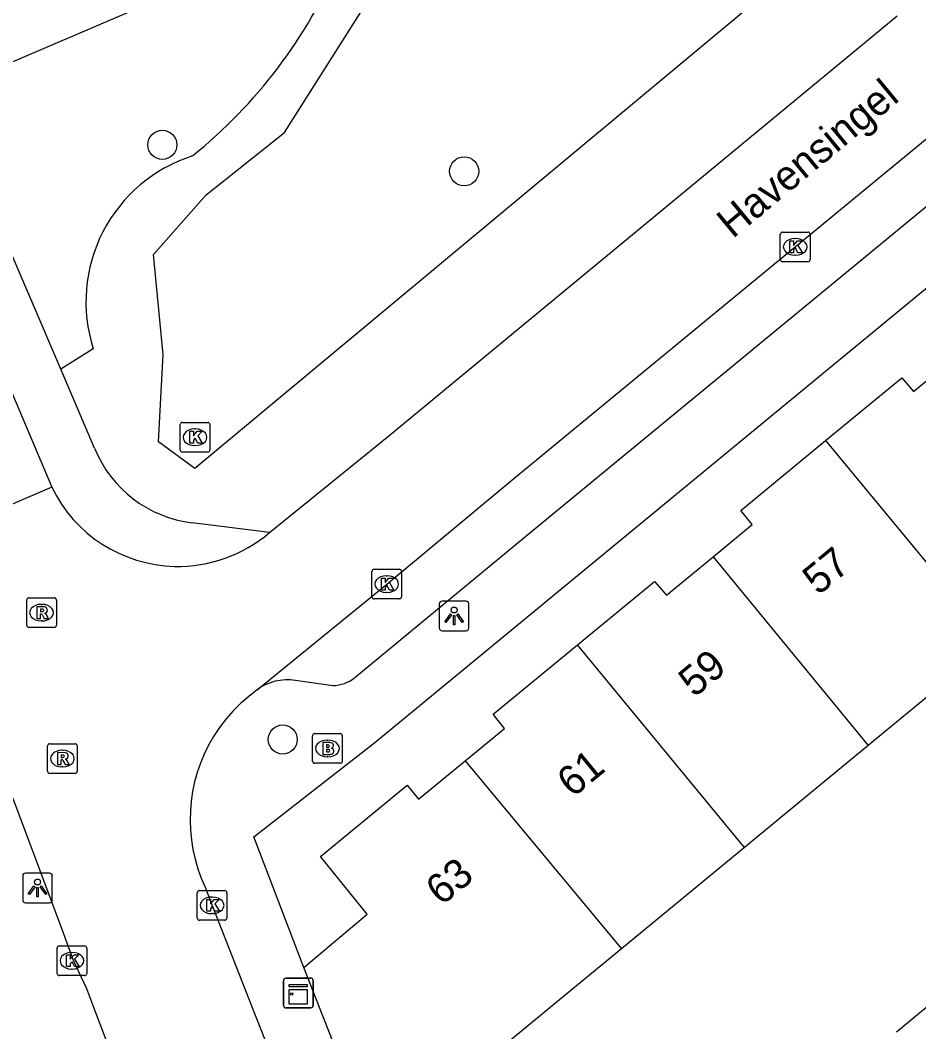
# Model space of a CAD drawing. Extents: x 161771 to 163125, y 382479 to 383177.
# Drawn here: x 161946.47 to 161976.75, y 382999.19 to 383033.26 of the extents above; entities that cross this region are included whole.
import ezdxf

# ---------------------------------------------------------------- set-up
doc = ezdxf.new("R2010")
doc.units = 0
for name, color, linetype in [('IMGEO_Boom', 7, 'Continuous'), ('IMGEO_Brandkraan', 7, 'Continuous'), ('IMGEO_Groenvoorziening', 7, 'Continuous'), ('IMGEO_Kast', 7, 'Continuous'), ('IMGEO_Kolk', 7, 'Continuous'), ('IMGEO_Lichtpunt', 7, 'Continuous'), ('IMGEO_Openbare_ruimte_label', 7, 'Continuous'), ('IMGEO_Pand', 7, 'Continuous'), ('IMGEO_Pand_nummerreeks', 7, 'Continuous'), ('IMGEO_Rijbaan_lokaal_open', 7, 'Continuous'), ('IMGEO_Rioolput', 7, 'Continuous'), ('IMGEO_Voetpad_open', 7, 'Continuous')]:
    doc.layers.add(name, color=color, linetype=linetype)

msp = doc.modelspace()

# ---------------------------------------------------------------- linework, layer by layer
at = {"layer": 'IMGEO_Boom'}
for centre in [(161951.257, 383029.066), (161961.429, 383028.173), (161955.314, 383009.031)]:
    msp.add_circle(centre, 0.489, dxfattribs=at)
at = {"layer": 'IMGEO_Brandkraan'}
for p, q in [((161956.397, 383009.229), (161957.249, 383009.229)), ((161956.322, 383008.303), (161956.322, 383009.155)), ((161956.81, 383009.009), (161956.835, 383009.009)), ((161957.323, 383009.155), (161957.323, 383008.303)), ((161957.249, 383008.229), (161956.397, 383008.229)), ((161956.833, 383008.449), (161956.808, 383008.449))]:
    msp.add_line(p, q, dxfattribs=at)
for points in [[(161956.397, 383009.229), (161957.249, 383009.229)], [(161956.322, 383008.303), (161956.322, 383009.155)], [(161956.67, 383008.929), (161956.67, 383008.529), (161956.883, 383008.529)], [(161956.901, 383008.929), (161956.67, 383008.929)], [(161957.323, 383009.155), (161957.323, 383008.303)], [(161956.849, 383008.848), (161956.795, 383008.848), (161956.795, 383008.772)], [(161956.795, 383008.772), (161956.848, 383008.772)], [(161956.857, 383008.696), (161956.795, 383008.696), (161956.795, 383008.615)], [(161956.795, 383008.615), (161956.857, 383008.615)], [(161957.249, 383008.229), (161956.397, 383008.229)]]:
    msp.add_lwpolyline(points, dxfattribs=at)
for centre, radius, start, end in [((161956.399, 383009.153), 0.0765, 91.552, 178.448), ((161956.399, 383009.153), 0.0765, 91.552, 178.448), ((161957.247, 383009.153), 0.0765, 1.552, 88.448), ((161957.247, 383009.153), 0.0765, 1.552, 88.448), ((161956.905, 383008.784), 0.145, 59.4692, 91.5367), ((161956.93, 383008.831), 0.0922, 285.5137, 58.1501), ((161956.85, 383008.81), 0.0379, 267.8285, 90.9355), ((161956.858, 383008.655), 0.0404, 269.8759, 90.5077), ((161956.889, 383008.78), 0.251, 268.6676, 293.5347), ((161956.935, 383008.639), 0.105, 301.3115, 78.989), ((161956.399, 383008.305), 0.0765, 181.552, 268.448), ((161956.399, 383008.305), 0.0765, 181.552, 268.448), ((161957.247, 383008.305), 0.0765, 271.552, 358.448), ((161957.247, 383008.305), 0.0765, 271.552, 358.448)]:
    msp.add_arc(centre, radius, start, end, dxfattribs=at)
for centre, major_axis, ratio, start_param, end_param in [((161956.809, 383008.729), (-0.387, 0.002), 0.722429, 4.712389, 7.853982), ((161956.834, 383008.729), (-0.39, 0.002), 0.717154, 1.570796, 4.712389)]:
    msp.add_ellipse(centre, major_axis=major_axis, ratio=ratio, start_param=start_param, end_param=end_param, dxfattribs=at)
at = {"layer": 'IMGEO_Groenvoorziening'}
for points in [[(161952.356, 383018.156), (161951.127, 383019.056), (161951.285, 383022), (161950.963, 383025.366), (161952.731, 383027.386), (161955.378, 383029.484), (161958.057, 383033.719), (161960.055, 383035.866), (161963.721, 383037.848), (161969.432, 383039.587), (161972.298, 383039.879), (161975.808, 383040.713), (161976.503, 383039.299), (161975.417, 383037.36), (161952.356, 383018.156)], [(161948.931, 383022.196), (161947.833, 383021.506)]]:
    msp.add_lwpolyline(points, dxfattribs=at)
for centre, radius, start, end in [((161941.63, 383041.898), 16.961, 308.8769, 336.7837), ((161953.848, 383023.775), 5.164, 107.7185, 197.8051)]:
    msp.add_arc(centre, radius, start, end, dxfattribs=at)
at = {"layer": 'IMGEO_Kast'}
for p, q in [((161955.339, 383000.065), (161955.339, 383000.906)), ((161955.339, 383000.906), (161955.339, 383000.065)), ((161955.414, 383000.99), (161956.255, 383000.99)), ((161956.255, 383000.99), (161955.414, 383000.99)), ((161956.339, 383000.915), (161956.339, 383000.074)), ((161956.339, 383000.074), (161956.339, 383000.915)), ((161956.264, 382999.99), (161955.423, 382999.99)), ((161955.423, 382999.99), (161956.264, 382999.99))]:
    msp.add_line(p, q, dxfattribs=at)
for points in [[(161955.534, 383000.78), (161956.134, 383000.78), (161956.134, 383000.695), (161955.534, 383000.695), (161955.534, 383000.78)], [(161955.534, 383000.605), (161956.134, 383000.605), (161956.134, 383000.116), (161955.534, 383000.116), (161955.534, 383000.605)]]:
    msp.add_lwpolyline(points, dxfattribs=at)
msp.add_circle((161955.618, 383000.454), 0.0377, dxfattribs=at)
for centre, start, end in [((161955.417, 383000.912), 92.4484, 184.2845), ((161955.417, 383000.912), 92.4484, 184.2845), ((161956.261, 383000.912), 2.4484, 94.2845), ((161956.261, 383000.912), 2.4484, 94.2845), ((161955.417, 383000.068), 182.4484, 274.2845), ((161955.417, 383000.068), 182.4484, 274.2845), ((161956.261, 383000.068), 272.4484, 4.2845), ((161956.261, 383000.068), 272.4484, 4.2845)]:
    msp.add_arc(centre, 0.0779, start, end, dxfattribs=at)
at = {"layer": 'IMGEO_Kolk'}
for p, q in [((161972.084, 383025.201), (161972.084, 383026.053)), ((161972.159, 383026.127), (161973.011, 383026.127)), ((161972.572, 383025.907), (161972.597, 383025.907)), ((161973.085, 383026.053), (161973.085, 383025.201)), ((161972.595, 383025.347), (161972.57, 383025.347)), ((161973.011, 383025.127), (161972.159, 383025.127)), ((161951.858, 383018.788), (161951.858, 383019.64)), ((161951.933, 383019.714), (161952.785, 383019.714)), ((161952.346, 383019.494), (161952.371, 383019.494)), ((161952.859, 383019.64), (161952.859, 383018.788)), ((161952.369, 383018.934), (161952.344, 383018.934)), ((161952.785, 383018.714), (161951.933, 383018.714)), ((161958.318, 383013.841), (161958.318, 383014.693)), ((161958.393, 383014.767), (161959.245, 383014.767)), ((161959.319, 383014.693), (161959.319, 383013.841)), ((161958.806, 383014.547), (161958.831, 383014.547)), ((161958.829, 383013.987), (161958.804, 383013.987)), ((161959.245, 383013.767), (161958.393, 383013.767)), ((161952.434, 383003.018), (161952.434, 383003.87)), ((161952.509, 383003.944), (161953.361, 383003.944)), ((161953.435, 383003.87), (161953.435, 383003.018)), ((161952.922, 383003.724), (161952.947, 383003.724)), ((161952.945, 383003.164), (161952.92, 383003.164)), ((161953.361, 383002.944), (161952.509, 383002.944)), ((161947.784, 383002.079), (161948.636, 383002.079)), ((161947.709, 383001.153), (161947.709, 383002.005)), ((161948.197, 383001.859), (161948.222, 383001.859)), ((161948.71, 383002.005), (161948.71, 383001.153)), ((161948.636, 383001.079), (161947.784, 383001.079)), ((161948.22, 383001.299), (161948.195, 383001.299))]:
    msp.add_line(p, q, dxfattribs=at)
for points in [[(161972.084, 383025.201), (161972.084, 383026.053)], [(161972.159, 383026.127), (161973.011, 383026.127)], [(161973.085, 383026.053), (161973.085, 383025.201)], [(161972.405, 383025.827), (161972.528, 383025.827), (161972.528, 383025.676), (161972.658, 383025.827), (161972.822, 383025.827), (161972.676, 383025.676), (161972.829, 383025.427), (161972.677, 383025.427), (161972.592, 383025.591), (161972.528, 383025.524), (161972.528, 383025.427), (161972.405, 383025.427), (161972.405, 383025.827)], [(161973.011, 383025.127), (161972.159, 383025.127)], [(161951.858, 383018.788), (161951.858, 383019.64)], [(161951.933, 383019.714), (161952.785, 383019.714)], [(161952.179, 383019.414), (161952.302, 383019.414), (161952.302, 383019.263), (161952.432, 383019.414), (161952.596, 383019.414), (161952.45, 383019.263), (161952.603, 383019.014), (161952.451, 383019.014), (161952.366, 383019.178), (161952.302, 383019.111), (161952.302, 383019.014), (161952.179, 383019.014), (161952.179, 383019.414)], [(161952.859, 383019.64), (161952.859, 383018.788)], [(161952.785, 383018.714), (161951.933, 383018.714)], [(161958.318, 383013.841), (161958.318, 383014.693)], [(161958.393, 383014.767), (161959.245, 383014.767)], [(161959.319, 383014.693), (161959.319, 383013.841)], [(161958.639, 383014.467), (161958.762, 383014.467), (161958.762, 383014.316), (161958.892, 383014.467), (161959.056, 383014.467), (161958.91, 383014.316), (161959.063, 383014.067), (161958.911, 383014.067), (161958.826, 383014.231), (161958.762, 383014.164), (161958.762, 383014.067), (161958.639, 383014.067), (161958.639, 383014.467)], [(161959.245, 383013.767), (161958.393, 383013.767)], [(161952.434, 383003.018), (161952.434, 383003.87)], [(161952.509, 383003.944), (161953.361, 383003.944)], [(161953.435, 383003.87), (161953.435, 383003.018)], [(161952.755, 383003.644), (161952.878, 383003.644), (161952.878, 383003.493), (161953.008, 383003.644), (161953.172, 383003.644), (161953.026, 383003.493), (161953.179, 383003.244), (161953.027, 383003.244), (161952.942, 383003.408), (161952.878, 383003.341), (161952.878, 383003.244), (161952.755, 383003.244), (161952.755, 383003.644)], [(161953.361, 383002.944), (161952.509, 383002.944)], [(161947.784, 383002.079), (161948.636, 383002.079)], [(161947.709, 383001.153), (161947.709, 383002.005)], [(161948.03, 383001.779), (161948.153, 383001.779), (161948.153, 383001.628), (161948.283, 383001.779), (161948.447, 383001.779), (161948.301, 383001.628), (161948.454, 383001.379), (161948.302, 383001.379), (161948.217, 383001.543), (161948.153, 383001.476), (161948.153, 383001.379), (161948.03, 383001.379), (161948.03, 383001.779)], [(161948.71, 383002.005), (161948.71, 383001.153)], [(161948.636, 383001.079), (161947.784, 383001.079)]]:
    msp.add_lwpolyline(points, dxfattribs=at)
for centre, start, end in [((161972.161, 383026.051), 91.552, 178.448), ((161972.161, 383026.051), 91.552, 178.448), ((161973.009, 383026.051), 1.552, 88.448), ((161973.009, 383026.051), 1.552, 88.448), ((161972.161, 383025.203), 181.552, 268.448), ((161972.161, 383025.203), 181.552, 268.448), ((161973.009, 383025.203), 271.552, 358.448), ((161973.009, 383025.203), 271.552, 358.448), ((161951.935, 383019.638), 91.552, 178.448), ((161951.935, 383019.638), 91.552, 178.448), ((161952.783, 383019.638), 1.552, 88.448), ((161952.783, 383019.638), 1.552, 88.448), ((161951.935, 383018.79), 181.552, 268.448), ((161951.935, 383018.79), 181.552, 268.448), ((161952.783, 383018.79), 271.552, 358.448), ((161952.783, 383018.79), 271.552, 358.448), ((161958.395, 383014.691), 91.552, 178.448), ((161958.395, 383014.691), 91.552, 178.448), ((161959.243, 383014.691), 1.552, 88.448), ((161959.243, 383014.691), 1.552, 88.448), ((161958.395, 383013.843), 181.552, 268.448), ((161958.395, 383013.843), 181.552, 268.448), ((161959.243, 383013.843), 271.552, 358.448), ((161959.243, 383013.843), 271.552, 358.448), ((161952.511, 383003.868), 91.552, 178.448), ((161952.511, 383003.868), 91.552, 178.448), ((161953.359, 383003.868), 1.552, 88.448), ((161953.359, 383003.868), 1.552, 88.448), ((161952.511, 383003.02), 181.552, 268.448), ((161952.511, 383003.02), 181.552, 268.448), ((161953.359, 383003.02), 271.552, 358.448), ((161953.359, 383003.02), 271.552, 358.448), ((161947.786, 383002.003), 91.552, 178.448), ((161947.786, 383002.003), 91.552, 178.448), ((161948.634, 383002.003), 1.552, 88.448), ((161948.634, 383002.003), 1.552, 88.448), ((161947.786, 383001.155), 181.552, 268.448), ((161947.786, 383001.155), 181.552, 268.448), ((161948.634, 383001.155), 271.552, 358.448), ((161948.634, 383001.155), 271.552, 358.448)]:
    msp.add_arc(centre, 0.0765, start, end, dxfattribs=at)
for centre, major_axis, ratio, start_param, end_param in [((161972.571, 383025.627), (-0.387, 0.002), 0.722429, 4.712389, 7.853982), ((161972.596, 383025.627), (-0.39, 0.002), 0.717154, 1.570796, 4.712389), ((161952.345, 383019.214), (-0.387, 0.002), 0.722429, 4.712389, 7.853982), ((161952.37, 383019.214), (-0.39, 0.002), 0.717154, 1.570796, 4.712389), ((161958.805, 383014.267), (-0.387, 0.002), 0.722429, 4.712389, 7.853982), ((161958.83, 383014.267), (-0.39, 0.002), 0.717154, 1.570796, 4.712389), ((161952.921, 383003.444), (-0.387, 0.002), 0.722429, 4.712389, 7.853982), ((161952.946, 383003.444), (-0.39, 0.002), 0.717154, 1.570796, 4.712389), ((161948.196, 383001.579), (-0.387, 0.002), 0.722429, 4.712389, 7.853982), ((161948.221, 383001.579), (-0.39, 0.002), 0.717154, 1.570796, 4.712389)]:
    msp.add_ellipse(centre, major_axis=major_axis, ratio=ratio, start_param=start_param, end_param=end_param, dxfattribs=at)
at = {"layer": 'IMGEO_Lichtpunt'}
for p, q in [((161961.493, 383013.692), (161960.685, 383013.692)), ((161961.493, 383013.692), (161960.685, 383013.692)), ((161960.591, 383013.597), (161960.591, 383012.79)), ((161960.591, 383013.597), (161960.591, 383012.79)), ((161961.587, 383012.79), (161961.587, 383013.597)), ((161961.587, 383012.79), (161961.587, 383013.597)), ((161960.685, 383012.696), (161961.493, 383012.696)), ((161960.685, 383012.696), (161961.493, 383012.696)), ((161946.554, 383004.434), (161946.554, 383003.627)), ((161946.554, 383004.434), (161946.554, 383003.627)), ((161947.456, 383004.529), (161946.648, 383004.529)), ((161947.456, 383004.529), (161946.648, 383004.529)), ((161947.55, 383003.627), (161947.55, 383004.434)), ((161947.55, 383003.627), (161947.55, 383004.434)), ((161946.648, 383003.533), (161947.456, 383003.533)), ((161946.648, 383003.533), (161947.456, 383003.533))]:
    msp.add_line(p, q, dxfattribs=at)
for points in [[(161960.965, 383013.261), (161961.004, 383013.233), (161960.816, 383012.971), (161960.778, 383012.998), (161960.965, 383013.261)], [(161961.067, 383013.213), (161961.114, 383013.213), (161961.114, 383012.891), (161961.067, 383012.891), (161961.067, 383013.213)], [(161961.177, 383013.233), (161961.215, 383013.26), (161961.402, 383012.998), (161961.363, 383012.97), (161961.177, 383013.233)], [(161946.928, 383004.098), (161946.967, 383004.07), (161946.779, 383003.808), (161946.741, 383003.835), (161946.928, 383004.098)], [(161947.14, 383004.07), (161947.178, 383004.097), (161947.365, 383003.835), (161947.326, 383003.807), (161947.14, 383004.07)], [(161947.03, 383004.05), (161947.077, 383004.05), (161947.077, 383003.728), (161947.03, 383003.728), (161947.03, 383004.05)]]:
    msp.add_lwpolyline(points, dxfattribs=at)
for centre in [(161961.09, 383013.395), (161947.053, 383004.232)]:
    msp.add_circle(centre, 0.0994, dxfattribs=at)
for centre, start, end in [((161960.685, 383013.597), 90, 180), ((161960.685, 383013.597), 90, 180), ((161961.493, 383013.597), 0, 90), ((161961.493, 383013.597), 0, 90), ((161960.685, 383012.79), 180, 270), ((161960.685, 383012.79), 180, 270), ((161961.493, 383012.79), 270, 0), ((161961.493, 383012.79), 270, 360), ((161946.648, 383004.434), 90, 180), ((161946.648, 383004.434), 90, 180), ((161947.456, 383004.434), 0, 90), ((161947.456, 383004.434), 0, 90), ((161946.648, 383003.627), 180, 270), ((161946.648, 383003.627), 180, 270), ((161947.456, 383003.627), 270, 0), ((161947.456, 383003.627), 270, 360)]:
    msp.add_arc(centre, 0.0946, start, end, dxfattribs=at)
at = {"layer": 'IMGEO_Pand'}
for points in [[(161973.604, 383019.1), (161976.175, 383021.217), (161976.572, 383020.753), (161978.169, 383022.07)], [(161969.817, 383015.19), (161971.137, 383016.279), (161970.748, 383016.749), (161973.604, 383019.1)], [(161973.604, 383019.1), (161979.244, 383012.292)], [(161965.253, 383012.221), (161967.848, 383014.357), (161968.245, 383013.893), (161969.817, 383015.19)], [(161969.817, 383015.19), (161975.045, 383008.831)], [(161979.244, 383012.292), (161975.045, 383008.831)], [(161961.463, 383008.312), (161962.786, 383009.402), (161962.409, 383009.881), (161965.253, 383012.221)], [(161970.879, 383005.397), (161965.253, 383012.221)], [(161975.045, 383008.831), (161970.879, 383005.397)], [(161956.028, 383001.349), (161958.162, 383003.149), (161956.591, 383005.087), (161959.503, 383007.488), (161959.891, 383007.018), (161961.463, 383008.312)], [(161961.463, 383008.312), (161966.727, 383001.975)], [(161970.879, 383005.397), (161966.727, 383001.975)], [(161966.727, 383001.975), (161964.33, 383000), (161958.463, 382995.164)], [(161976.002, 382999.183), (161978.654, 383001.368), (161980.026, 382999.704), (161977.374, 382997.519)], [(161958.463, 382995.164), (161956.559, 383000), (161956.028, 383001.349)]]:
    msp.add_lwpolyline(points, dxfattribs=at)
at = {"layer": 'IMGEO_Rijbaan_lokaal_open'}
for points in [[(161954.449, 383010.709), (161958.818, 383014.267), (161963.107, 383017.828), (161972.581, 383025.628), (161988.094, 383038.411), (162000, 383048.208), (162014.364, 383060.022)], [(161954.865, 383016.001), (161958.887, 383019.257), (161976.018, 383033.407)], [(161943.177, 383027.812), (161947.533, 383017.528)], [(161947.533, 383017.528), (161942.983, 383015.58)], [(161949.478, 382998.607), (161949.428, 382998.734), (161948.95, 383000), (161948.711, 383000.633), (161948.26, 383001.581), (161947.885, 383002.626), (161946.34, 383006.744), (161944.007, 383012.809), (161943.332, 383014.713), (161942.983, 383015.58)], [(161954.449, 383010.709), (161954.28, 383010.571)], [(161952.702, 383004.056), (161952.934, 383003.444), (161954.29, 383000), (161959.699, 382986.261), (161966.823, 382968.082), (161968.383, 382964.151)]]:
    msp.add_lwpolyline(points, dxfattribs=at)
for centre, radius, start, end in [((161951.789, 383019.593), 4.731, 205.8845, 268.5695), ((161951.784, 383019.601), 4.738, 268.6327, 310.5568), ((161957.547, 383006.332), 5.352, 127.6167, 148.4879), ((161957.548, 383006.331), 5.354, 148.4899, 205.1467)]:
    msp.add_arc(centre, radius, start, end, dxfattribs=at)
at = {"layer": 'IMGEO_Rioolput'}
for p, q in [((161946.686, 383012.879), (161946.686, 383013.731)), ((161946.761, 383013.805), (161947.613, 383013.805)), ((161947.687, 383013.731), (161947.687, 383012.879)), ((161947.174, 383013.585), (161947.199, 383013.585)), ((161947.197, 383013.025), (161947.172, 383013.025)), ((161947.613, 383012.805), (161946.761, 383012.805)), ((161947.464, 383008.889), (161948.316, 383008.889)), ((161947.389, 383007.963), (161947.389, 383008.815)), ((161947.877, 383008.669), (161947.902, 383008.669)), ((161948.39, 383008.815), (161948.39, 383007.963)), ((161948.316, 383007.889), (161947.464, 383007.889)), ((161947.9, 383008.109), (161947.875, 383008.109))]:
    msp.add_line(p, q, dxfattribs=at)
for points in [[(161946.686, 383012.879), (161946.686, 383013.731)], [(161946.761, 383013.805), (161947.613, 383013.805)], [(161947.687, 383013.731), (161947.687, 383012.879)], [(161947.275, 383013.503), (161947.023, 383013.505), (161947.023, 383013.105)], [(161947.201, 383013.424), (161947.147, 383013.424), (161947.147, 383013.343)], [(161947.147, 383013.343), (161947.199, 383013.343)], [(161947.023, 383013.105), (161947.147, 383013.105), (161947.147, 383013.267), (161947.158, 383013.267)], [(161947.205, 383013.238), (161947.276, 383013.105), (161947.416, 383013.105), (161947.351, 383013.231)], [(161947.613, 383012.805), (161946.761, 383012.805)], [(161947.464, 383008.889), (161948.316, 383008.889)], [(161947.389, 383007.963), (161947.389, 383008.815)], [(161947.978, 383008.587), (161947.726, 383008.589), (161947.726, 383008.189)], [(161947.904, 383008.508), (161947.85, 383008.508), (161947.85, 383008.427)], [(161948.39, 383008.815), (161948.39, 383007.963)], [(161947.726, 383008.189), (161947.85, 383008.189), (161947.85, 383008.351), (161947.861, 383008.351)], [(161947.85, 383008.427), (161947.902, 383008.427)], [(161947.908, 383008.322), (161947.979, 383008.189), (161948.119, 383008.189), (161948.054, 383008.315)], [(161948.316, 383007.889), (161947.464, 383007.889)]]:
    msp.add_lwpolyline(points, dxfattribs=at)
for centre, radius, start, end in [((161946.763, 383013.729), 0.0765, 91.552, 178.448), ((161946.763, 383013.729), 0.0765, 91.552, 178.448), ((161947.611, 383013.729), 0.0765, 1.552, 88.448), ((161947.611, 383013.729), 0.0765, 1.552, 88.448), ((161947.183, 383013.532), 0.19, 274.7715, 282.9687), ((161947.207, 383013.328), 0.0964, 77.0061, 93.1865), ((161947.221, 383013.385), 0.0378, 276.6634, 79.6772), ((161947.274, 383013.393), 0.109, 350.3612, 89.416), ((161947.272, 383013.393), 0.112, 277.5842, 350.9817), ((161947.256, 383013.178), 0.108, 29.5134, 73.7905), ((161947.157, 383013.214), 0.0533, 26.0293, 88.6989), ((161946.763, 383012.881), 0.0765, 181.552, 268.448), ((161946.763, 383012.881), 0.0765, 181.552, 268.448), ((161947.611, 383012.881), 0.0765, 271.552, 358.448), ((161947.611, 383012.881), 0.0765, 271.552, 358.448), ((161947.466, 383008.813), 0.0765, 91.552, 178.448), ((161947.466, 383008.813), 0.0765, 91.552, 178.448), ((161948.314, 383008.813), 0.0765, 1.552, 88.448), ((161948.314, 383008.813), 0.0765, 1.552, 88.448), ((161947.91, 383008.412), 0.0964, 77.0061, 93.1865), ((161947.977, 383008.477), 0.109, 350.3612, 89.416), ((161947.86, 383008.298), 0.0533, 26.0293, 88.6989), ((161947.886, 383008.616), 0.19, 274.7715, 282.9687), ((161947.924, 383008.469), 0.0378, 276.6634, 79.6772), ((161947.975, 383008.477), 0.112, 277.5842, 350.9817), ((161947.959, 383008.262), 0.108, 29.5134, 73.7905), ((161947.466, 383007.965), 0.0765, 181.552, 268.448), ((161947.466, 383007.965), 0.0765, 181.552, 268.448), ((161948.314, 383007.965), 0.0765, 271.552, 358.448), ((161948.314, 383007.965), 0.0765, 271.552, 358.448)]:
    msp.add_arc(centre, radius, start, end, dxfattribs=at)
for centre, major_axis, ratio, start_param, end_param in [((161947.173, 383013.305), (-0.387, 0.002), 0.722429, 4.712389, 7.853982), ((161947.198, 383013.305), (-0.39, 0.002), 0.717154, 1.570796, 4.712389), ((161947.876, 383008.389), (-0.387, 0.002), 0.722429, 4.712389, 7.853982), ((161947.901, 383008.389), (-0.39, 0.002), 0.717154, 1.570796, 4.712389)]:
    msp.add_ellipse(centre, major_axis=major_axis, ratio=ratio, start_param=start_param, end_param=end_param, dxfattribs=at)
at = {"layer": 'IMGEO_Voetpad_open'}
for points in [[(161956.028, 383001.349), (161954.345, 383005.756), (161958.418, 383008.932), (162000, 383043.194), (162019.717, 383059.44)], [(162013.207, 383056.799), (162000, 383045.919), (161963.694, 383016.025), (161957.739, 383011.105)], [(161947.833, 383021.506), (161943.83, 383030.854), (161950.431, 383033.665), (161956.251, 383036.199)], [(161948.972, 383018.847), (161947.833, 383021.506)], [(161954.865, 383016.001), (161952.263, 383016.332)], [(161957.007, 383010.845), (161955.742, 383011.021)]]:
    msp.add_lwpolyline(points, dxfattribs=at)
for centre, radius, start, end in [((161952.752, 383020.382), 4.08, 202.1066, 263.1188), ((161955.48, 383009.27), 1.771, 81.5055, 125.6267), ((161956.923, 383012.241), 1.398, 273.4275, 305.6817)]:
    msp.add_arc(centre, radius, start, end, dxfattribs=at)

# ---------------------------------------------------------------- texts
at = {"layer": 'IMGEO_Openbare_ruimte_label'}
msp.add_text('Havensingel', height=1, rotation=39.6442, dxfattribs=at).set_placement((161970.477, 383025.884))
at = {"layer": 'IMGEO_Pand_nummerreeks'}
for s, rotation, p in [('57', 39.4791, (161973.364, 383013.866)), ('59', 39.4791, (161969.182, 383010.422)), ('61', 39.4791, (161965.089, 383007.049)), ('63', 39.4711, (161960.665, 383003.406))]:
    msp.add_text(s, height=1, rotation=rotation, dxfattribs=at).set_placement(p)

doc.saveas('drawing.dxf')
